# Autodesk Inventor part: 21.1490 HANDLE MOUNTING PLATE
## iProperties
Created: 2012-03
Part Number: 21.1490 HANDLE MOUNTING PLATE
Document SubType Name: Modeling
Designer: Administrator
Density: 7.85 g/cm^3
Material: Steel
Mass: 149.853 g
Surface Area: 60.3453 cm^2
Volume: 19.0896 cm^3
Author: Administrator
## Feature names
1. Base1
